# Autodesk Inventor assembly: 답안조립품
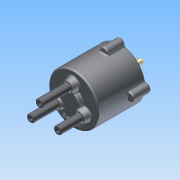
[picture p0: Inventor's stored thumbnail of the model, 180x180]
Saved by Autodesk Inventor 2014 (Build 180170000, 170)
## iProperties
Created: 2015-09
Part Number: 답안조립품
Document SubType Name: Assembly
Designer: study
Mass: 1860.19 g
Surface Area: 1801.23 cm^2
Volume: 438.525 cm^3
Density: 4.24192 g/cm^3
Author: study
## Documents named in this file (14)
- C:\Users\study\Desktop\350916V1018\답안조립품.iam
- C:\Users\study\Desktop\350916V1018\몸체.ipt
- C:\Users\study\Desktop\350916V1018\커버.ipt
- C:\Users\study\Desktop\350916V1018\메인 축.ipt
- C:\Users\study\Desktop\350916V1018\판캠.ipt
- C:\Users\study\Desktop\350916V1018\슬라이드 축.ipt
- C:\Users\study\Desktop\350916V1018\베어링 NA 4900.ipt
- C:\Users\study\Desktop\350916V1018\오일실.ipt
- C:\Users\study\Desktop\350916V1018\멈춤링 10 x 1.ipt
- C:\Users\study\Desktop\350916V1018\멈춤링 22 x 1.2.ipt
- C:\Users\study\Desktop\350916V1018\M5x0.8x20.ipt
- C:\Users\study\Desktop\350916V1018\가변 스프링 - 01(가변부품).ipt
- C:\Users\study\Desktop\350916V1018\가변 스프링 - 02(가변부품).ipt
- C:\Users\study\Desktop\350916V1018\가변 스프링 - 03(가변부품).ipt
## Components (7 placed, 4 different names)
1. 가변 스프링 - 01(가변부품):1
2. 가변 스프링 - 02(가변부품):1
3. 가변 스프링 - 03(가변부품):1
4. M5x0.8x20:1
5. M5x0.8x20:2
6. M5x0.8x20:3
7. M5x0.8x20:4
